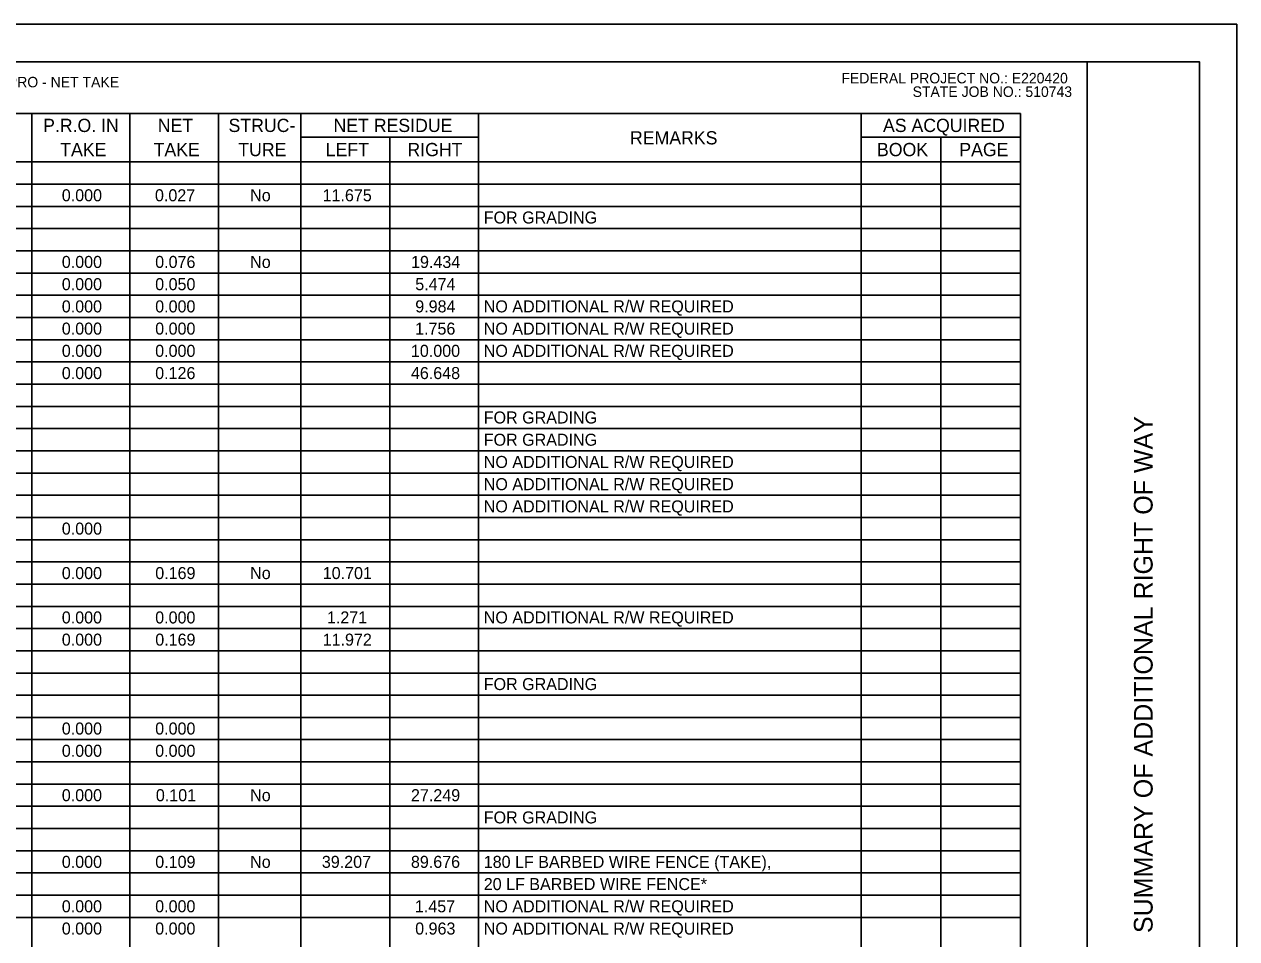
# Model space of a CAD drawing. Extents: x -1.7 to 34, y -55.6 to 22.
# Drawn here: x 17.78 to 34, y 9.78 to 22 of the extents above; entities that cross this region are included whole.
import ezdxf

# ---------------------------------------------------------------- set-up
doc = ezdxf.new("R2010")
doc.units = 0
for name, color, linetype in [('SH_Border', 7, 'Continuous'), ('SH_Cut_Line', 7, 'Continuous'), ('SH_Data', 7, 'Continuous'), ('SH_Text', 7, 'Continuous')]:
    doc.layers.add(name, color=color, linetype=linetype)

msp = doc.modelspace()

# ---------------------------------------------------------------- linework, layer by layer
at = {"layer": 'SH_Border'}
msp.add_line((32, 0.5), (32, 21.5), dxfattribs=at)
msp.add_lwpolyline([(1.5, 21.5), (33.5, 21.5), (33.5, 0.5), (1.5, 0.5)], close=True, dxfattribs=at)
at = {"layer": 'SH_Cut_Line'}
msp.add_lwpolyline([(0, 0), (34, 0), (34, 22), (0, 22)], close=True, dxfattribs=at)
at = {"layer": 'SH_Text'}
for p, q in [((1.5, 20.806), (31.109, 20.806)), ((17.885, 20.806), (17.885, 3.233)), ((19.196, 20.806), (19.196, 3.233)), ((20.383, 20.806), (20.383, 3.233)), ((21.484, 20.806), (21.484, 3.233)), ((23.86, 20.806), (23.86, 3.233)), ((28.978, 20.806), (28.978, 3.233)), ((31.109, 20.806), (31.109, 3.233)), ((21.484, 20.492), (23.86, 20.492)), ((22.672, 20.492), (22.672, 3.233)), ((28.978, 20.492), (31.109, 20.492)), ((30.044, 20.492), (30.044, 3.233)), ((1.5, 20.16), (31.109, 20.16)), ((1.5, 19.863), (31.109, 19.863)), ((1.5, 19.566), (31.109, 19.566)), ((1.5, 19.269), (31.109, 19.269)), ((1.5, 18.972), (31.109, 18.972)), ((1.5, 18.675), (31.109, 18.675)), ((1.5, 18.378), (31.109, 18.378)), ((1.5, 18.081), (31.109, 18.081)), ((1.5, 17.784), (31.109, 17.784)), ((1.5, 17.487), (31.109, 17.487)), ((1.5, 17.19), (31.109, 17.19)), ((1.5, 16.893), (31.109, 16.893)), ((1.5, 16.596), (31.109, 16.596)), ((1.5, 16.299), (31.109, 16.299)), ((1.5, 16.002), (31.109, 16.002)), ((1.5, 15.705), (31.109, 15.705)), ((1.5, 15.408), (31.109, 15.408)), ((1.5, 15.111), (31.109, 15.111)), ((1.5, 14.814), (31.109, 14.814)), ((1.5, 14.517), (31.109, 14.517)), ((1.5, 14.22), (31.109, 14.22)), ((1.5, 13.923), (31.109, 13.923)), ((1.5, 13.626), (31.109, 13.626)), ((1.5, 13.329), (31.109, 13.329)), ((1.5, 13.032), (31.109, 13.032)), ((1.5, 12.736), (31.109, 12.736)), ((1.5, 12.439), (31.109, 12.439)), ((1.5, 12.142), (31.109, 12.142)), ((1.5, 11.845), (31.109, 11.845)), ((1.5, 11.548), (31.109, 11.548)), ((1.5, 11.251), (31.109, 11.251)), ((1.5, 10.954), (31.109, 10.954)), ((1.5, 10.657), (31.109, 10.657)), ((1.5, 10.36), (31.109, 10.36)), ((1.5, 10.063), (31.109, 10.063))]:
    msp.add_line(p, q, dxfattribs=at)

# ---------------------------------------------------------------- texts
at = {"layer": 'SH_Data'}
msp.add_text('SUMMARY OF ADDITIONAL RIGHT OF WAY', height=0.25, rotation=90, dxfattribs=at).set_placement((32.875, 9.854))
at = {"layer": 'SH_Text'}
for s, height, p in [('NET RESIDUE = RECORD AREA - TOTAL PRO - NET TAKE', 0.14, (13.899, 21.157)), ('FEDERAL PROJECT NO.: E220420', 0.14, (28.713, 21.21)), ('STATE JOB NO.: 510743', 0.14, (29.665, 21.029)), ('P.R.O. IN', 0.1768, (18.037, 20.56)), ('NET', 0.1768, (19.571, 20.56)), ('STRUC-', 0.1768, (20.517, 20.56)), ('NET RESIDUE', 0.17678, (21.921, 20.56)), ('AS ACQUIRED', 0.17678, (29.269, 20.56)), ('REMARKS', 0.1768, (25.886, 20.394)), ('TAKE', 0.1768, (18.266, 20.237)), ('TAKE', 0.1768, (19.515, 20.237)), ('TURE', 0.1768, (20.647, 20.237)), ('LEFT', 0.1768, (21.816, 20.237)), ('RIGHT', 0.1768, (22.909, 20.237)), ('BOOK', 0.1768, (29.189, 20.237)), ('PAGE', 0.1768, (30.29, 20.237)), ('0.000', 0.1607, (18.287, 19.634)), ('0.027', 0.1607, (19.533, 19.634)), ('No', 0.1607, (20.806, 19.634)), ('11.675', 0.1607, (21.775, 19.634)), ('FOR GRADING', 0.16071, (23.93, 19.337)), ('0.000', 0.1607, (18.287, 18.743)), ('0.076', 0.1607, (19.536, 18.743)), ('No', 0.1607, (20.806, 18.743)), ('19.434', 0.1607, (22.958, 18.743)), ('0.000', 0.1607, (18.287, 18.446)), ('0.050', 0.1607, (19.536, 18.446)), ('5.474', 0.1607, (23.014, 18.446)), ('0.000', 0.1607, (18.287, 18.149)), ('0.000', 0.1607, (19.536, 18.149)), ('9.984', 0.1607, (23.014, 18.149)), ('NO ADDITIONAL R/W REQUIRED', 0.16071, (23.93, 18.149)), ('0.000', 0.1607, (18.287, 17.852)), ('0.000', 0.1607, (19.536, 17.852)), ('1.756', 0.1607, (23.012, 17.852)), ('NO ADDITIONAL R/W REQUIRED', 0.16071, (23.93, 17.852)), ('0.000', 0.1607, (18.287, 17.555)), ('0.000', 0.1607, (19.536, 17.555)), ('10.000', 0.1607, (22.956, 17.555)), ('NO ADDITIONAL R/W REQUIRED', 0.16071, (23.93, 17.555)), ('0.000', 0.1607, (18.287, 17.258)), ('0.126', 0.1607, (19.536, 17.258)), ('46.648', 0.1607, (22.956, 17.258)), ('FOR GRADING', 0.16071, (23.93, 16.664)), ('FOR GRADING', 0.16071, (23.93, 16.367)), ('NO ADDITIONAL R/W REQUIRED', 0.16071, (23.93, 16.07)), ('NO ADDITIONAL R/W REQUIRED', 0.16071, (23.93, 15.773)), ('NO ADDITIONAL R/W REQUIRED', 0.16071, (23.93, 15.476)), ('0.000', 0.1607, (18.287, 15.179)), ('0.000', 0.1607, (18.287, 14.585)), ('0.169', 0.1607, (19.537, 14.585)), ('No', 0.1607, (20.806, 14.585)), ('10.701', 0.1607, (21.777, 14.585)), ('0.000', 0.1607, (18.287, 13.992)), ('0.000', 0.1607, (19.536, 13.992)), ('1.271', 0.1607, (21.833, 13.992)), ('NO ADDITIONAL R/W REQUIRED', 0.16071, (23.93, 13.992)), ('0.000', 0.1607, (18.287, 13.695)), ('0.169', 0.1607, (19.537, 13.695)), ('11.972', 0.1607, (21.776, 13.695)), ('FOR GRADING', 0.16071, (23.93, 13.101)), ('0.000', 0.1607, (18.287, 12.507)), ('0.000', 0.1607, (19.536, 12.507)), ('0.000', 0.1607, (18.287, 12.21)), ('0.000', 0.1607, (19.536, 12.21)), ('0.000', 0.1607, (18.287, 11.616)), ('0.101', 0.1607, (19.545, 11.616)), ('No', 0.1607, (20.806, 11.616)), ('27.249', 0.1607, (22.957, 11.616)), ('FOR GRADING', 0.16071, (23.93, 11.319)), ('0.000', 0.1607, (18.287, 10.725)), ('0.109', 0.1607, (19.537, 10.725)), ('No', 0.1607, (20.806, 10.725)), ('39.207', 0.1607, (21.765, 10.725)), ('89.676', 0.1607, (22.956, 10.725)), ('180 LF BARBED WIRE FENCE (TAKE),', 0.16071, (23.93, 10.725)), ('20 LF BARBED WIRE FENCE*', 0.16071, (23.93, 10.428)), ('0.000', 0.1607, (18.287, 10.131)), ('0.000', 0.1607, (19.536, 10.131)), ('1.457', 0.1607, (23.009, 10.131)), ('NO ADDITIONAL R/W REQUIRED', 0.16071, (23.93, 10.131)), ('0.000', 0.1607, (18.287, 9.834)), ('0.000', 0.1607, (19.536, 9.834)), ('0.963', 0.1607, (23.013, 9.834)), ('NO ADDITIONAL R/W REQUIRED', 0.16071, (23.93, 9.834))]:
    msp.add_text(s, height=height, dxfattribs=at).set_placement(p)

doc.saveas('drawing.dxf')
